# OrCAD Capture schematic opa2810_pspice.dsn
size A
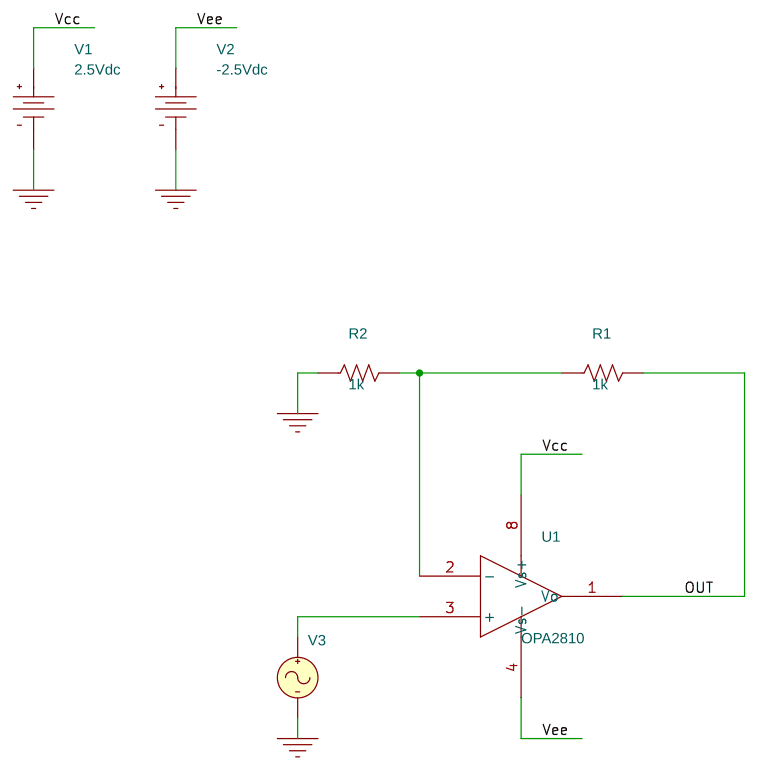
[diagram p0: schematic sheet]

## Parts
R1  1k  [AX/RC05]
R2  1k  [AX/RC05]
U1  OPA2810
V1  VDC
V2  VDC
V3  VAC

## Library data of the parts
R1 R2 = R
U1 = OPA2810
V1 = VDC: DC: 2.5Vdc
V2 = VDC: DC: -2.5Vdc
V3 = VAC

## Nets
Vcc: U1.8(Vs+) V1.0(+)
Vee: U1.4(Vs-) V2.0(+)
0: R2.1 V1.1(-) V2.1(-) V3.2(-)
OUT: R1.2 U1.1(Vo)
N01130: U1.3(+) V3.1(+)
N01240: R1.1 R2.2 U1.2(-)
